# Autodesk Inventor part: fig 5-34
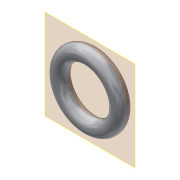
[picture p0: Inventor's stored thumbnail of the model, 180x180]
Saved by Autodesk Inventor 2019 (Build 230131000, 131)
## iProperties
Created: 2010-02
Part Number: fig 5-34
Document SubType Name: Modeling
Designer: CADSoft
Density: 1 g/cm^3
Material: Generic
Appearance: Default
Author: CADSoft
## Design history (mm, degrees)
sketch "Sketch1"
  geometry: L1 (0, 21.37)-(0, -16.247); C1 r 5 at (20.026, 0); 1 further point
  constraints: 2 end point, 1 centre point
  dimensions: "d0" = 10 diameter of C1
revolve "Revolution1" sketch "Sketch1" stored, may be unused: angle "d1" = 90 deg
workplane "Work Plane1"
body "Solid1"
